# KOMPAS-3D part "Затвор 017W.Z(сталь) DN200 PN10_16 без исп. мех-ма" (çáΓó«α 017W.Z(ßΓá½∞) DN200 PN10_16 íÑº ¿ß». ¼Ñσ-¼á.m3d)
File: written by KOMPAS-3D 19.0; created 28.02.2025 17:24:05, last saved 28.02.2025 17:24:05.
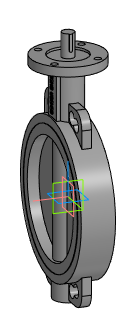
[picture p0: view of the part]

Document properties: Автор: Евгений; Полное имя файла: E:\Dendor Работа Сачек\3D для проекитирвщиков\1.5 Тип 017W.Z Сталь Затвор дисковый поворотный Межфланцевый\stp_Тип 017W.Z(сталь). Затвор без исполн. механизма\Затвор 017W.Z(сталь) DN200 PN10_16 без исп. мех-ма.m3d

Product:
- Part/product: Затвор 017W.Z(сталь) DN200 PN10_16 без исп. мех-ма

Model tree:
1. Операция без истории:1  (labels: Затвор 017W.Z(сталь) DN200 PN10_16 без исп. мех-ма)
